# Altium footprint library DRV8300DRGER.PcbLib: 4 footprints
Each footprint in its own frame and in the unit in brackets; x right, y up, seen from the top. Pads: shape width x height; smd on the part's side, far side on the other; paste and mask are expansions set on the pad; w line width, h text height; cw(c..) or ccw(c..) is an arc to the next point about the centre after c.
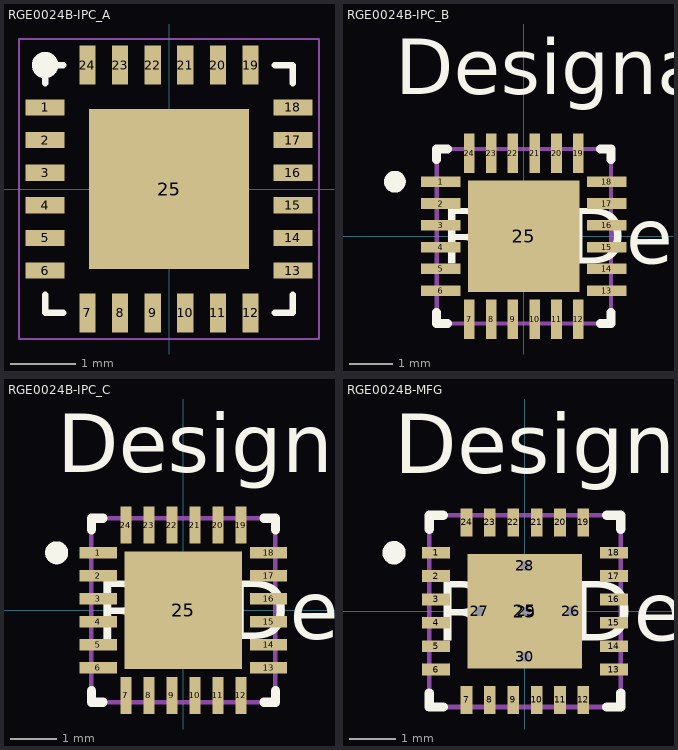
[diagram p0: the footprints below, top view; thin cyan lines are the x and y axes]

## RGE0024B-IPC_A [mm]
pads (25):
  rect 0.6x0.25 smd paste+0 mask+0.051: 1(-1.9,1.25) 2(-1.9,0.75) 3(-1.9,0.25) 4(-1.9,-0.25) 5(-1.9,-0.75) 6(-1.9,-1.25) 13(1.9,-1.25) 14(1.9,-0.75) 15(1.9,-0.25) 16(1.9,0.25) 17(1.9,0.75) 18(1.9,1.25)
  rect 0.25x0.6 smd paste+0 mask+0.051: 7(-1.25,-1.9) 8(-0.75,-1.9) 9(-0.25,-1.9) 10(0.25,-1.9) 11(0.75,-1.9) 12(1.25,-1.9) 19(1.25,1.9) 20(0.75,1.9) 21(0.25,1.9) 22(-0.25,1.9) 23(-0.75,1.9) 24(-1.25,1.9)
  rect 2.45x2.45 smd paste-1.262 mask+0: 25(0,0)
Top Overlay:
  circle w0.254: c-1.9,1.9 r0.076
  lines w0.102: -1.9,-1.625 -1.9,-1.9 -1.625,-1.9 ; -1.9,1.625 -1.9,1.9 -1.625,1.9 ; 1.625,-1.9 1.9,-1.9 1.9,-1.625 ; 1.625,1.9 1.9,1.9 1.9,1.625
Top Paste:
  region: -0.806,0.806 -0.806,-0.806 0.806,-0.806 0.806,0.806
Mechanical 1:
  lines w0.025: -2.3,-2.3 -2.3,2.3 2.3,2.3 2.3,-2.3 -2.3,-2.3

## RGE0024B-IPC_B [mm]
pads (25):
  rect 0.91x0.242 smd paste+0 mask+0: 1(-1.901,1.25) 2(-1.901,0.75) 3(-1.901,0.25) 4(-1.901,-0.25) 5(-1.901,-0.75) 6(-1.901,-1.25) 13(1.901,-1.25) 14(1.901,-0.75) 15(1.901,-0.25) 16(1.901,0.25) 17(1.901,0.75) 18(1.901,1.25)
  rect 0.242x0.91 smd paste+0 mask+0: 7(-1.25,-1.901) 8(-0.75,-1.901) 9(-0.25,-1.901) 10(0.25,-1.901) 11(0.75,-1.901) 12(1.25,-1.901) 19(1.25,1.901) 20(0.75,1.901) 21(0.25,1.901) 22(-0.25,1.901) 23(-0.75,1.901) 24(-1.25,1.901)
  rect 2.55x2.55 smd paste-1.262 mask+0: 25(0,0)
Top Overlay:
  circle w0.25: c-2.956,1.25 r0.125
  lines w0.2: -2,-1.75 -2,-2 -1.75,-2 ; -2,1.75 -2,2 -1.75,2 ; 1.75,-2 2,-2 2,-1.75 ; 1.75,2 2,2 2,1.75
  text "Designator452" at -2.946,3.251 h1.27
  text "RefDes" at -1.905,-0.635 h1.27
Top Paste:
  region: -0.806,0.806 -0.806,-0.806 0.806,-0.806 0.806,0.806
Mechanical 13:
  lines w0.1: -2,-2 -2,2 2,2 2,-2 -2,-2

## RGE0024B-IPC_C [mm]
pads (25):
  rect 0.81x0.242 smd paste+0 mask+0: 1(-1.851,1.25) 2(-1.851,0.75) 3(-1.851,0.25) 4(-1.851,-0.25) 5(-1.851,-0.75) 6(-1.851,-1.25) 13(1.851,-1.25) 14(1.851,-0.75) 15(1.851,-0.25) 16(1.851,0.25) 17(1.851,0.75) 18(1.851,1.25)
  rect 0.242x0.81 smd paste+0 mask+0: 7(-1.25,-1.851) 8(-0.75,-1.851) 9(-0.25,-1.851) 10(0.25,-1.851) 11(0.75,-1.851) 12(1.25,-1.851) 19(1.25,1.851) 20(0.75,1.851) 21(0.25,1.851) 22(-0.25,1.851) 23(-0.75,1.851) 24(-1.25,1.851)
  rect 2.55x2.55 smd paste-1.262 mask+0: 25(0,0)
Top Overlay:
  circle w0.25: c-2.756,1.25 r0.125
  lines w0.2: -2,-1.75 -2,-2 -1.75,-2 ; -2,1.75 -2,2 -1.75,2 ; 1.75,-2 2,-2 2,-1.75 ; 1.75,2 2,2 2,1.75
  text "Designator451" at -2.743,2.997 h1.27
  text "RefDes" at -1.905,-0.635 h1.27
Top Paste:
  region: -0.806,0.806 -0.806,-0.806 0.806,-0.806 0.806,0.806
Mechanical 13:
  lines w0.1: -2,-2 -2,2 2,2 2,-2 -2,-2

## RGE0024B-MFG [mm]
pads (30):
  rect 0.6x0.25 smd paste+0 mask+0: 1(-1.9,1.25) 2(-1.9,0.75) 3(-1.9,0.25) 4(-1.9,-0.25) 5(-1.9,-0.75) 6(-1.9,-1.25) 13(1.9,-1.25) 14(1.9,-0.75) 15(1.9,-0.25) 16(1.9,0.25) 17(1.9,0.75) 18(1.9,1.25)
  rect 0.25x0.6 smd paste+0 mask+0: 7(-1.25,-1.9) 8(-0.75,-1.9) 9(-0.25,-1.9) 10(0.25,-1.9) 11(0.75,-1.9) 12(1.25,-1.9) 19(1.25,1.9) 20(0.75,1.9) 21(0.25,1.9) 22(-0.25,1.9) 23(-0.75,1.9) 24(-1.25,1.9)
  rect 2.45x2.45 smd paste-1.212 mask+0: 25(0,0)
  round 0.5 / inner round 1.524 / far side round 0.5 hole 0.203 paste-2539.97 mask+0: 26(0.975,0) 27(-0.975,0) 28(0,0.975) 29(0.025,0) 30(0,-0.975)
Top Overlay:
  circle w0.25: c-2.8,1.25 r0.125
  lines w0.2: -2.05,-1.75 -2.05,-2.05 -1.75,-2.05 ; -2.05,1.75 -2.05,2.05 -1.75,2.05 ; 1.75,-2.05 2.05,-2.05 2.05,-1.75 ; 1.75,2.05 2.05,2.05 2.05,1.75
  text "Designator450" at -2.794,2.946 h1.27
  text "RefDes" at -1.905,-0.635 h1.27
Top Paste:
  region: 1.13,-0.1 1.18,-0.15 1.18,-1.13 1.13,-1.18 0.15,-1.18 0.1,-1.13 0.1,-0.15 0.15,-0.1
  region: -0.15,-0.1 -0.1,-0.15 -0.1,-1.13 -0.15,-1.18 -1.13,-1.18 -1.18,-1.13 -1.18,-0.15 -1.13,-0.1
  region: 1.13,1.18 1.18,1.13 1.18,0.15 1.13,0.1 0.15,0.1 0.1,0.15 0.1,1.13 0.15,1.18
  region: -0.15,1.18 -0.1,1.13 -0.1,0.15 -0.15,0.1 -1.13,0.1 -1.18,0.15 -1.18,1.13 -1.13,1.18
Mechanical 13:
  lines w0.1: -2.05,-2.05 -2.05,2.05 2.05,2.05 2.05,-2.05 -2.05,-2.05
